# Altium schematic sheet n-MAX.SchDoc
size A4; PageSetup: Record=PageOptions¦CenterHorizontal=True¦CenterVertical=True¦PrintScale=1.00¦XCorrection=1.00¦YCorrection=1.00¦PrintKind=2¦BorderSize=5000000¦LeftOffset=0¦BottomOffset=0¦Orientation=2¦PaperLength=1000¦PaperWidth=1000¦Scale=100¦PaperSource=7¦PrintQuality=-4¦MediaType=1¦DitherType=10¦PaperKind=A4¦PrintScaleMode=1
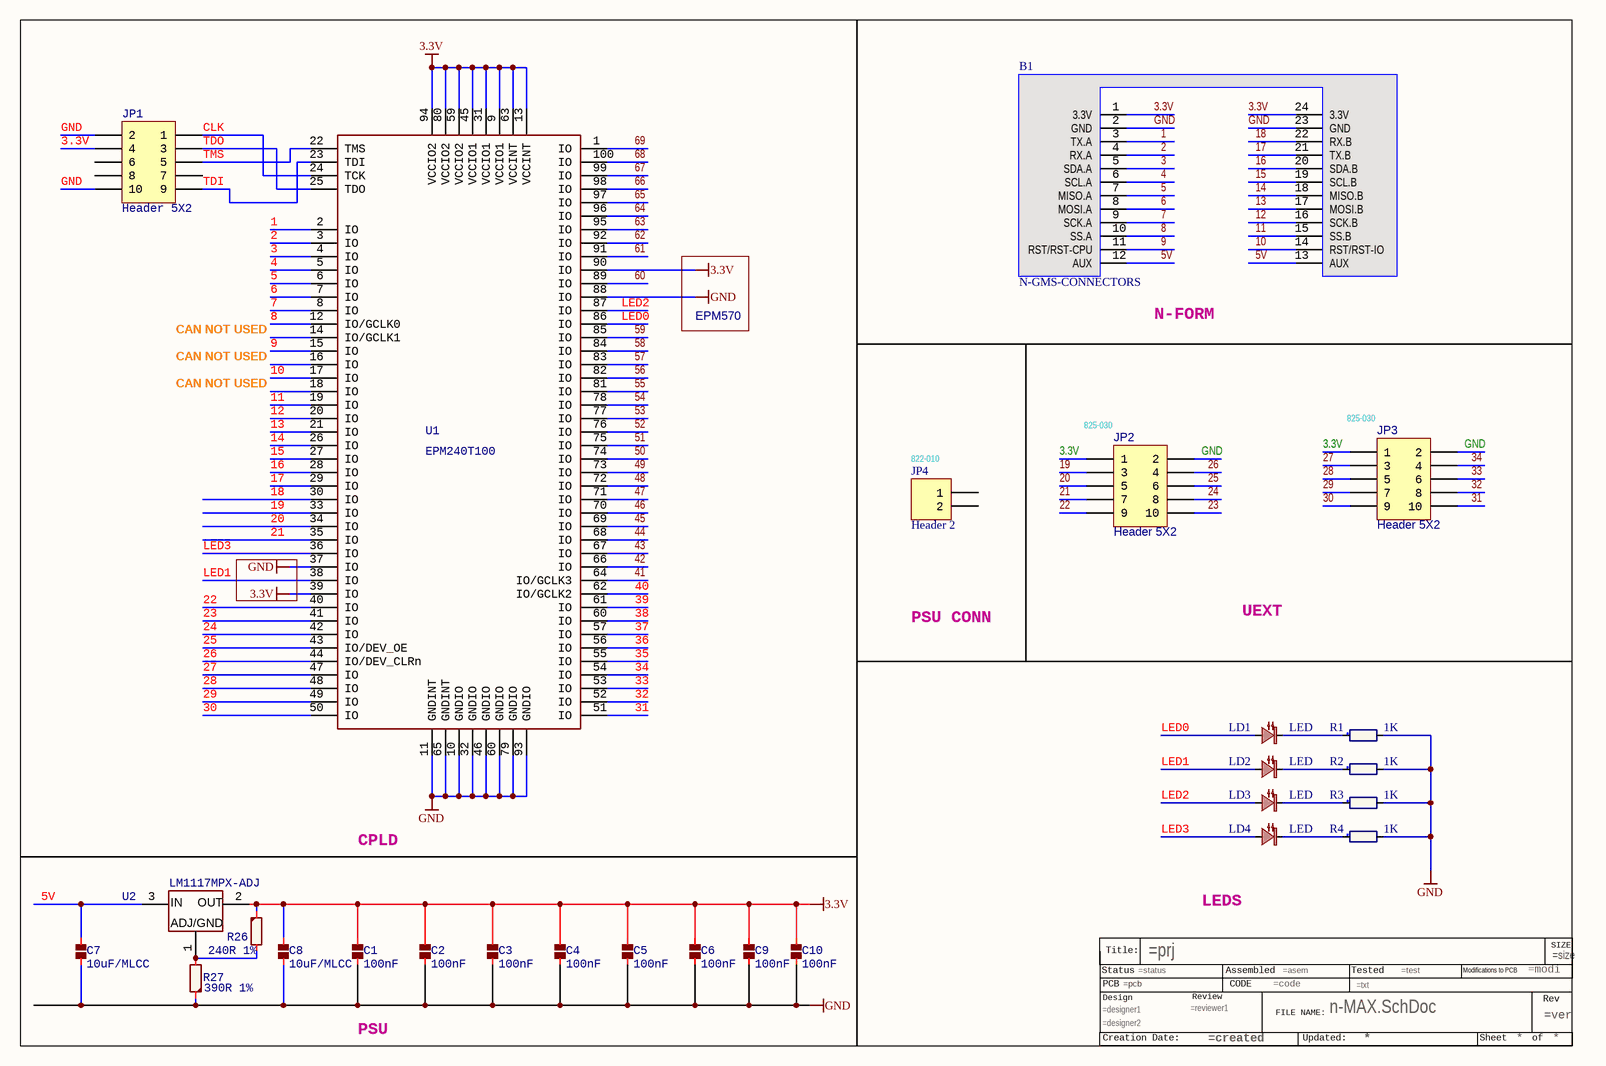
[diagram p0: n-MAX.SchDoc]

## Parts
?*??  FILE_NAME: n-MAX.SchDoc  (hidden comment: TITLEBLOCK3)  (graphical)
B1  N-GMS-CONNECTORS  [N-GMS]
C1  100nF  [0603_CAP]
C2  100nF  [0603_CAP]
C3  100nF  [0603_CAP]
C4  100nF  [0603_CAP]
C5  100nF  [0603_CAP]
C6  100nF  [0603_CAP]
C7  10uF/MLCC  [0603_CAP]
C8  10uF/MLCC  [0603_CAP]
C9  100nF  [0603_CAP]
C10  100nF  [0603_CAP]
JP1  Header 5X2  [ML10]
JP2  Header 5X2  CODE: 825-030  [ML10-FCI]
JP3  Header 5X2  CODE: 825-030  [ML10-FCI]
JP4  Header 2  CODE: 822-010  [MOLEX-705430001]
LD1  LED  [0603_LED_RED]
LD2  LED  [0603_LED_RED]
LD3  LED  [0603_LED_RED]
LD4  LED  [0603_LED_RED]
R1  1K  [0603_res]
R2  1K  [0603_res]
R3  1K  [0603_res]
R4  1K  [0603_res]
R26  240R 1%  [0603_RES]
R27  390R 1%  [0603_RES]
U1  EPM240T100  [TQFP100]
U2  LM1117MPX-ADJ  [SOT-223]

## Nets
3.3V: B1.1(3.3V) B1.24(3.3V) C1.1 C2.1 C3.1 C4.1 C5.1 C6.1 C8.1 C9.1 C10.1 JP1.4 JP2.1 JP3.1 R26.1 U1.9(VCCIO1) U1.13(VCCINT) U1.31(VCCIO1) U1.39(IO) U1.45(VCCIO1) U1.59(VCCIO2) U1.63(VCCINT) U1.80(VCCIO2) U1.90(IO) U1.94(VCCIO2) U2.2(OUT)
GND: B1.2(GND) B1.23(GND) C1.2 C2.2 C3.2 C4.2 C5.2 C6.2 C7.2 C8.2 C9.2 C10.2 JP1.2 JP1.10 JP2.2 JP3.2 R1.2 R2.2 R3.2 R4.2 R27.1 U1.10(GNDIO) U1.11(GNDINT) U1.32(GNDIO) U1.37(IO) U1.46(GNDIO) U1.60(GNDIO) U1.65(GNDINT) U1.79(GNDIO) U1.88(IO) U1.93(GNDIO)
1: B1.3(TX.A) U1.2(IO)
2: B1.4(RX.A) U1.3(IO)
3: B1.5(SDA.A) U1.4(IO)
4: B1.6(SCL.A) U1.5(IO)
5: B1.7(MISO.A) U1.6(IO)
5V: B1.12(AUX) B1.13(AUX) C7.1 U2.3(IN)
6: B1.8(MOSI.A) U1.7(IO)
7: B1.9(SCK.A) U1.8(IO)
8: B1.10(SS.A) U1.12(IO/GCLK0)
9: B1.11(RST/RST-CPU) U1.15(IO)
10: B1.14(RST/RST-IO) U1.17(IO)
11: B1.15(SS.B) U1.19(IO)
12: B1.16(SCK.B) U1.20(IO)
13: B1.17(MOSI.B) U1.21(IO)
14: B1.18(MISO.B) U1.26(IO)
15: B1.19(SCL.B) U1.27(IO)
16: B1.20(SDA.B) U1.28(IO)
17: B1.21(TX.B) U1.29(IO)
18: B1.22(RX.B) U1.30(IO)
19: JP2.3 U1.33(IO)
20: JP2.5 U1.34(IO)
21: JP2.7 U1.35(IO)
22: JP2.9 U1.40(IO)
23: JP2.10 U1.41(IO)
24: JP2.8 U1.42(IO)
25: JP2.6 U1.43(IO/DEV_OE)
26: JP2.4 U1.44(IO/DEV_CLRn)
27: JP3.3 U1.47(IO)
28: JP3.5 U1.48(IO)
29: JP3.7 U1.49(IO)
30: JP3.9 U1.50(IO)
31: JP3.10 U1.51(IO)
32: JP3.8 U1.52(IO)
33: JP3.6 U1.53(IO)
34: JP3.4 U1.54(IO)
35: U1.55(IO)
36: U1.56(IO)
37: U1.57(IO)
38: U1.60(IO)
39: U1.61(IO)
40: U1.62(IO/GCLK2)
41: U1.64(IO/GCLK3)
42: U1.66(IO)
43: U1.67(IO)
44: U1.68(IO)
45: U1.69(IO)
46: U1.70(IO)
47: U1.71(IO)
48: U1.72(IO)
49: U1.73(IO)
50: U1.74(IO)
51: U1.75(IO)
52: U1.76(IO)
53: U1.77(IO)
54: U1.78(IO)
55: U1.81(IO)
56: U1.82(IO)
57: U1.83(IO)
58: U1.84(IO)
59: U1.85(IO)
60: U1.89(IO)
61: U1.91(IO)
62: U1.92(IO)
63: U1.95(IO)
64: U1.96(IO)
65: U1.97(IO)
66: U1.98(IO)
67: U1.99(IO)
68: U1.100(IO)
69: U1.1(IO)
CLK: JP1.1 U1.24(TCK)
LED0: LD1.1(A) U1.86(IO)
LED1: LD2.1(A) U1.38(IO)
LED2: LD3.1(A) U1.87(IO)
LED3: LD4.1(A) U1.36(IO)
TDI: JP1.9 U1.23(TDI)
TDO: JP1.3 U1.25(TDO)
TMS: JP1.5 U1.22(TMS)
NetLD1_2: LD1.2(C) R1.1
NetLD2_2: LD2.2(C) R2.1
NetLD3_2: LD3.2(C) R3.1
NetLD4_2: LD4.2(C) R4.1
NetR26_2: R26.2 R27.2 U2.1(ADJ/GND)

Not connected (* = marked no-connect by the designer): ?*?? ?1; JP1 6 7 8; JP4 1 2; U1 14(IO/GCLK1) 16(IO) 18(IO)

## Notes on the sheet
- EPM570
- (near B1) N-FORM
- CAN NOT USED
- PSU CONN
- UEXT
- CPLD
- LEDS
- PSU

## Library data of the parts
C1-C10 = C: CAPACITOR
JP1-JP3 = Header 5X2: Header, 5-Pin, Dual row
JP4 = Header 2: Header, 2-Pin
R1-R4 = R: RESISTOR
R26 R27 = R: RESISTOR; OLIMEX: OLIMEX#33 RES 0805 10 K 5%
U2 = LM1117: REGULATOR LOW DROPOUT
